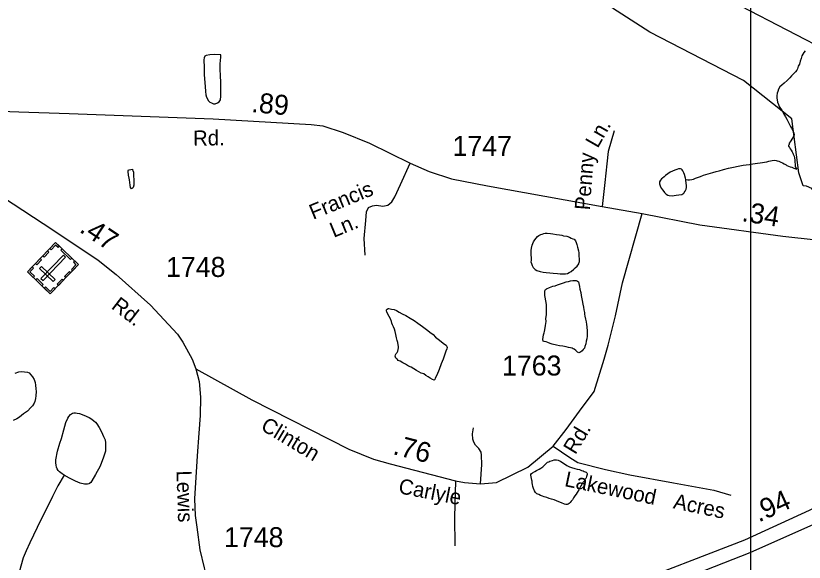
# Model space of a CAD drawing. Extents: x 2126262 to 2293712, y 749403 to 919119.
# Drawn here: x 2220963 to 2225896, y 772432 to 775853 of the extents above; entities that cross this region are included whole.
import ezdxf

# ---------------------------------------------------------------- set-up
doc = ezdxf.new("R2010")
doc.units = 0
for name, color, linetype in [('Exist Cultural Cemetery CELL', 7, 'Continuous'), ('Exist Hydrographic Creek Single Shore', 7, 'Continuous'), ('Exist Hydrographic Misc Water Feature', 7, 'Continuous'), ('Exist Road Non-System Type 51', 7, 'Continuous'), ('Exist Road Non-System Type 51 Label', 7, 'Continuous'), ('Exist Road Primary US Divided Attributed', 7, 'Continuous'), ('Exist Road Primary US Mileage Hundredths English Label', 7, 'Continuous'), ('Exist Road Secondary Mileage Hundredths English Label', 7, 'Continuous'), ('Exist Road Secondary Type 51 Attributed', 7, 'Continuous'), ('Exist Road Secondary Type 51 Label', 7, 'Continuous'), ('Exist Road Secondary Type 51 Number Label', 7, 'Continuous'), ('Map Preparation Inset Cut Line', 7, 'Continuous')]:
    doc.layers.add(name, color=color, linetype=linetype)

msp = doc.modelspace()

# ---------------------------------------------------------------- linework, layer by layer
at = {"layer": 'Exist Cultural Cemetery CELL'}
for points in [[(2221179.4, 774111.4), (2221035.8, 774249.4), (2221212.3, 774433), (2221355.8, 774295)], [(2221236.2, 774410), (2221228.2, 774401.7), (2221212.4, 774417), (2221184.4, 774387.8), (2221176.3, 774395.5), (2221212.3, 774433)], [(2221170.4, 774373), (2221140.4, 774341.8), (2221132.2, 774349.6), (2221162.2, 774380.9)], [(2221306.4, 774326.5), (2221245.3, 774385.3), (2221253.2, 774393.5), (2221314.3, 774334.7)], [(2221124.7, 774325.5), (2221094.7, 774294.2), (2221086.5, 774302.1), (2221116.5, 774333.4)], [(2221121.1, 774208.1), (2221134.5, 774195.2), (2221275.1, 774341.3), (2221261.6, 774354.3)], [(2221065.8, 774280.7), (2221074, 774272.8), (2221051.7, 774249.6), (2221081, 774221.5), (2221073.2, 774213.5), (2221035.8, 774249.5)], [(2221197.1, 774188.8), (2221210, 774202.2), (2221125.2, 774283.8), (2221112.2, 774270.4)], [(2221331.9, 774317.9), (2221324, 774309.6), (2221339.8, 774294.3), (2221311.8, 774265.2), (2221319.9, 774257.5), (2221355.8, 774294.9)], [(2221307.4, 774244.5), (2221277.4, 774213.3), (2221269.2, 774221.2), (2221299.2, 774252.4)], [(2221126, 774162.8), (2221088.6, 774198.7), (2221096.5, 774206.9), (2221133.9, 774171)], [(2221260.8, 774196.1), (2221230.8, 774164.9), (2221222.6, 774172.8), (2221252.6, 774204)], [(2221209.4, 774142.6), (2221201.2, 774150.5), (2221178.9, 774127.3), (2221149.7, 774155.4), (2221141.9, 774147.4), (2221179.4, 774111.4)]]:
    msp.add_lwpolyline(points, close=True, dxfattribs=at)
at = {"layer": 'Exist Hydrographic Creek Single Shore'}
msp.add_lwpolyline([(2225985.9, 774387), (2225979.9, 774406.6), (2225972.7, 774423.7), (2225976.8, 774466.1), (2225985.3, 774509.9), (2225969, 774563.2), (2225976.4, 774612.2), (2225958.7, 774657.9), (2225952.1, 774702.5), (2225968.5, 774735.1), (2225943.4, 774771), (2225910.8, 774785.1), (2225890.1, 774788.4), (2225862, 774869), (2225817.9, 775207.8), (2225515.9, 775446.9), (2224929.8, 775750.9), (2224695.9, 775900.1), (2224661.8, 775972.9), (2224570, 776056.9), (2224418.9, 776122.3)], dxfattribs=at)
at = {"layer": 'Exist Hydrographic Misc Water Feature'}
for points in [[(2222141.4, 775482.2), (2222148, 775410.1), (2222150.5, 775378.6), (2222152.7, 775358.4), (2222156.4, 775342.4), (2222168.9, 775320.6), (2222176.9, 775312.5), (2222188.6, 775306.6), (2222200.9, 775300.7), (2222210.7, 775300.9), (2222224.9, 775306.9), (2222236.8, 775314.8), (2222244.8, 775327), (2222246.2, 775349.1), (2222246.2, 775387.2), (2222245.8, 775431.1), (2222243.5, 775482.9), (2222243.1, 775511), (2222242.9, 775549.2), (2222244.8, 775574.9), (2222246.6, 775590.8), (2222246.6, 775609), (2222206.4, 775610.6), (2222178.5, 775608.4), (2222155, 775604.2), (2222146.6, 775600.2), (2222142.9, 775590.2), (2222140.8, 775576.3), (2222141.4, 775528.4), (2222141.4, 775482.2)], [(2225902.1, 775632.4), (2225894.5, 775622.6), (2225888.1, 775612.6), (2225882.2, 775602.5), (2225876.7, 775584.3), (2225870.5, 775568.2), (2225867.2, 775550), (2225858.8, 775536.3), (2225853.3, 775520.1), (2225849.4, 775512.2), (2225841.4, 775502), (2225831.3, 775490.2), (2225817.4, 775476), (2225805.5, 775463.6), (2225789.7, 775447.7), (2225771.7, 775431.4), (2225755.9, 775417.6), (2225744.4, 775407.1), (2225736.2, 775393.4), (2225730.5, 775379.2), (2225726.2, 775367.3), (2225724.9, 775351.2), (2225724.7, 775337.1), (2225727, 775325.4), (2225729.2, 775311.3), (2225735, 775297.4), (2225739.5, 775285.4), (2225743.2, 775277.5)], [(2225743.2, 775277.5), (2225755.5, 775261.5), (2225767.4, 775241.4), (2225779.9, 775219.7), (2225787.7, 775205.9), (2225795.9, 775188), (2225803.9, 775171.8), (2225810.2, 775159.9), (2225816.4, 775148), (2225822.5, 775136.1), (2225826.2, 775128.2), (2225830.5, 775118.3), (2225832.4, 775108.3), (2225832.8, 775104.1), (2225828.7, 775096.3), (2225822.7, 775086.2), (2225818.6, 775079.9), (2225812.7, 775069.9), (2225809.2, 775063.9), (2225802.8, 775055.9), (2225801, 775047.7), (2225799.1, 775043.9), (2225797.1, 775039.8), (2225798.9, 775035.8), (2225803.3, 775027.9), (2225809.2, 775020.1), (2225815.3, 775011.8), (2225821.5, 775000), (2225825.2, 774992.1), (2225827.2, 774986.1), (2225832, 774978.1), (2225833.8, 774974.2), (2225835.4, 774964.2), (2225837.9, 774948.4), (2225838.1, 774936.2), (2225840, 774924.2), (2225840.4, 774914.4), (2225840.2, 774910.3), (2225842.2, 774904.4), (2225844.5, 774900.3), (2225850.2, 774892.2)], [(2225155.3, 774826.7), (2225167.2, 774824.9), (2225179.1, 774824.7), (2225193, 774827.1), (2225203.3, 774829.2), (2225217, 774835.2), (2225235.1, 774841.4), (2225247.1, 774847.3), (2225266.6, 774855.7), (2225281, 774859.7), (2225294.7, 774863.7), (2225324.7, 774872.1), (2225344.8, 774878), (2225364.6, 774882.3), (2225390.7, 774890.6), (2225422.7, 774898.7), (2225454.3, 774905.3), (2225482.1, 774911.3), (2225514.1, 774917.4), (2225532.4, 774919.9), (2225553.9, 774921.9), (2225574.2, 774926.2), (2225604.1, 774930.1), (2225620.3, 774932.6), (2225635.9, 774934.7), (2225648.2, 774936.5), (2225662.2, 774938.8), (2225673.9, 774942.7), (2225695.8, 774947.1), (2225708.1, 774949.3), (2225720, 774947.1), (2225727.8, 774945.1), (2225737.8, 774941.6), (2225749.9, 774935.3), (2225760, 774931.3), (2225770, 774925.8), (2225782.3, 774919.9), (2225788.3, 774915.7), (2225797.9, 774911.9), (2225808.4, 774907.9), (2225818.2, 774903.9), (2225832.2, 774898.1), (2225850.2, 774892.2)], [(2221668, 774859.1), (2221666.1, 774873.2), (2221665.9, 774883), (2221669.6, 774887.3), (2221673.7, 774889.1), (2221693.8, 774891.4), (2221693.8, 774887.3), (2221695.9, 774883.3), (2221700.2, 774873.3), (2221700.4, 774849.4), (2221702.2, 774827.2), (2221702.4, 774805.2), (2221702.6, 774791.4), (2221698.5, 774777.4), (2221694.4, 774773.2), (2221686.6, 774769.1), (2221680.7, 774777.3), (2221678.2, 774793.1), (2221674.1, 774824.9), (2221670.4, 774845.4), (2221668.4, 774851.4), (2221668, 774859.1)], [(2225155.3, 774826.7), (2225153, 774836.8), (2225146.9, 774858.4), (2225142.6, 774868.4), (2225140.7, 774874.3), (2225136.4, 774882.7), (2225132.7, 774888.5), (2225128.8, 774892.4), (2225122.7, 774894.5), (2225116.7, 774894.2), (2225108.7, 774894.2), (2225098.7, 774890), (2225086.6, 774886.2), (2225072.9, 774880.1), (2225058.5, 774873.8), (2225042.7, 774863.6), (2225028.8, 774853.5), (2225019.1, 774843.6), (2225009.3, 774835.4), (2225003.1, 774831.4), (2224997, 774823.4), (2224991, 774813.4), (2224991.7, 774801.1), (2224995.3, 774787.2), (2225001.9, 774773.2), (2225011.7, 774761.6), (2225021.8, 774745.5), (2225031.8, 774735.8), (2225041.9, 774729.8), (2225052.1, 774727.9), (2225070, 774726), (2225095.8, 774730.2), (2225111.8, 774732.2), (2225129.7, 774734.4), (2225142.2, 774742.7), (2225145.6, 774746.6), (2225151.8, 774754.6), (2225157.5, 774766.7), (2225159.2, 774776.6), (2225159.4, 774790.8), (2225157.1, 774804.5), (2225155.1, 774822.7), (2225155.3, 774826.7)], [(2224187.6, 774307.9), (2224189.7, 774323.8), (2224189.7, 774336), (2224187.4, 774357.9), (2224187.2, 774382.2), (2224189.1, 774398.6), (2224195, 774416.7), (2224202.6, 774437.1), (2224210.4, 774450.9), (2224218.6, 774461.1), (2224228.2, 774471.4), (2224236.7, 774477.4), (2224248.1, 774483.4), (2224256.1, 774485.4), (2224266.2, 774489.6), (2224276.4, 774491.7), (2224288.1, 774491.5), (2224308.2, 774489.7), (2224324.2, 774488.1), (2224345.9, 774484), (2224364.2, 774480.4), (2224380.4, 774478.4), (2224390.4, 774474.5), (2224410.5, 774472.6), (2224428.2, 774466.7), (2224438.2, 774460.8), (2224448.7, 774456.8), (2224456.5, 774453.1), (2224464.7, 774443), (2224468.4, 774433.1), (2224472.9, 774421), (2224477, 774405), (2224483.1, 774380.6), (2224485.4, 774368.4), (2224485.4, 774348.2), (2224487.4, 774330), (2224487.4, 774310.1)], [(2224187.6, 774307.9), (2224194, 774289.9), (2224200.2, 774276), (2224212, 774264.1), (2224224.3, 774258.2), (2224244.2, 774252.3), (2224263.9, 774246.5), (2224282.4, 774244.5), (2224304.1, 774242.8), (2224326.5, 774240.7), (2224352.1, 774239.3), (2224368.3, 774237.2), (2224388.4, 774237.5), (2224402.3, 774237.4), (2224414.2, 774239.7), (2224426.3, 774245.9), (2224438.2, 774251.8), (2224453.8, 774266.1), (2224463.6, 774274), (2224475.7, 774285.9), (2224485.4, 774300.3), (2224487.4, 774310.1)], [(2224507.1, 774070.6), (2224511.6, 774046.4), (2224515.9, 774028.8), (2224517.8, 774012.6), (2224522.1, 773994.6), (2224522.1, 773984.8), (2224524.3, 773972.7), (2224528.2, 773952.6), (2224532.7, 773936.5), (2224534.4, 773920.9), (2224536.8, 773904.7), (2224538.9, 773878.8), (2224538.9, 773861), (2224537.5, 773846.6), (2224535.2, 773830.7), (2224531.5, 773816.6), (2224529.9, 773798.6), (2224523.9, 773783), (2224521.7, 773772.7), (2224513.7, 773762.6), (2224506.1, 773754.8), (2224496, 773746.6), (2224490.3, 773744.6), (2224486, 773742.4), (2224478.2, 773746.4), (2224466.3, 773756.3), (2224456.1, 773766), (2224449.9, 773768.1), (2224443.8, 773771.9), (2224433.9, 773773.8), (2224422, 773776), (2224406, 773779.6), (2224385.9, 773783.5), (2224365.6, 773787.4), (2224345.9, 773791.2), (2224320.1, 773797), (2224307.6, 773801), (2224291.6, 773806.6), (2224281.6, 773810.6), (2224269.7, 773812.8), (2224263.9, 773816.5), (2224261.7, 773826.6), (2224263.1, 773840.5), (2224265.6, 773854.8), (2224269.3, 773866.8), (2224271.3, 773876.7), (2224275, 773898.8), (2224276.8, 773912.7), (2224278.7, 773926.6), (2224280.7, 773938.5), (2224280.3, 773956.8), (2224282.4, 773968.7), (2224284.2, 773982.6), (2224284.2, 773994.8), (2224284.2, 774012.6), (2224283.8, 774026.5), (2224283.6, 774042.7), (2224281.8, 774056.8), (2224279.9, 774068.4), (2224275.4, 774090.6), (2224273.4, 774100.7), (2224273.4, 774108.4), (2224272.9, 774116.5), (2224273.2, 774122.6), (2224273.2, 774130.7), (2224275.2, 774134.5), (2224277, 774138.6), (2224282.8, 774142.6), (2224302.9, 774151), (2224323, 774158.9), (2224339, 774163), (2224352.7, 774169), (2224372.4, 774175.4), (2224390.4, 774181.6), (2224406.8, 774187.6), (2224420.8, 774189.6), (2224434.5, 774194), (2224448.5, 774195.9), (2224460.4, 774196.1), (2224468.6, 774196.1), (2224478.4, 774192.2), (2224484.8, 774186.4), (2224486.4, 774176.4), (2224490.7, 774158.3), (2224492.8, 774140.2), (2224499.3, 774120.5), (2224501.4, 774102.3), (2224507.1, 774070.6)], [(2223507.1, 773906.4), (2223541.3, 773882.6), (2223553.4, 773872.7), (2223573.7, 773857), (2223589.7, 773841.2), (2223606.1, 773827.4), (2223623.8, 773813.4), (2223637.9, 773803.5), (2223646.3, 773797.8), (2223655.9, 773789.8), (2223660.3, 773781.9), (2223662.1, 773775.9), (2223660.5, 773767.7), (2223654.1, 773753.6), (2223646.7, 773733.6), (2223636.9, 773703.4), (2223625.2, 773673.6), (2223611.4, 773637.5), (2223597.7, 773603.1), (2223588.1, 773583.1), (2223584.2, 773575.1), (2223580.1, 773571.3), (2223569.6, 773574.9), (2223556.1, 773585), (2223543.8, 773593), (2223529.8, 773600.8), (2223515.7, 773610.6), (2223499.7, 773616.3), (2223485.8, 773624.4), (2223471.2, 773632.3), (2223453.4, 773641.9), (2223437.6, 773652), (2223421, 773659.8), (2223400.9, 773671.8), (2223385.1, 773679.4), (2223369.1, 773689.6), (2223356.8, 773695.4), (2223351, 773701.2), (2223346.9, 773705), (2223340.8, 773709.2), (2223338.9, 773715.2), (2223336.9, 773721.2), (2223338.5, 773729), (2223342.6, 773737.4), (2223348.6, 773745.4), (2223352.9, 773753.2), (2223356.2, 773763.3), (2223358.2, 773773.1), (2223358.4, 773781.2), (2223356.2, 773793.3), (2223354.1, 773807), (2223349.8, 773819), (2223345.9, 773837), (2223343.9, 773847.1), (2223341.6, 773857.2), (2223337.7, 773876.8), (2223333.2, 773890.9), (2223327.5, 773905.1), (2223321.1, 773917.1), (2223317, 773929), (2223313.3, 773938.9), (2223306.9, 773954.9), (2223298.9, 773970.7), (2223290.5, 773984.5), (2223284.4, 773998.5), (2223283, 774004.4), (2223282.5, 774012.5), (2223286.6, 774016.8), (2223292.4, 774020.8), (2223298.3, 774020.7), (2223314.3, 774016.7), (2223330.1, 774013), (2223344.5, 774006.8), (2223362.9, 773997.2), (2223380.8, 773987.2), (2223402.7, 773975.8), (2223431, 773959.7), (2223456.8, 773944), (2223479.2, 773928.1), (2223507.1, 773906.4)], [(2220958.7, 773615.7), (2220982.7, 773623.9), (2221000.7, 773626), (2221018.4, 773624.2), (2221036.4, 773620.7), (2221046.9, 773616.7), (2221058.5, 773604.8), (2221068.8, 773592.7), (2221079.1, 773574.9), (2221085.4, 773556.9), (2221086.8, 773540.8), (2221089.3, 773516.9), (2221091.4, 773500.8), (2221089.7, 773473.1), (2221085.8, 773457), (2221081.9, 773436.9), (2221077.8, 773427), (2221068.2, 773410.6), (2221058.1, 773400.7), (2221036.6, 773378.4), (2221012.2, 773360.6), (2220986.4, 773340.2), (2220970.6, 773330), (2220946.4, 773319.8)], [(2221267.1, 772976.1), (2221253.1, 772984.3), (2221237.2, 772998.1), (2221229.2, 773006.2), (2221222.6, 773016.1), (2221218.9, 773026), (2221216.4, 773040.2), (2221214.6, 773053.8), (2221214.6, 773071.7), (2221223.8, 773127.9), (2221239.6, 773176.2), (2221249.7, 773205.9), (2221263.4, 773260.2), (2221276.9, 773306.1), (2221288.4, 773334.3), (2221294.4, 773344.4), (2221306.5, 773356.3), (2221312.2, 773360.3), (2221318.6, 773364.3), (2221326.6, 773366.7), (2221336.2, 773366.4), (2221348.3, 773364.6), (2221362.4, 773362.9), (2221388.5, 773352.9), (2221422.3, 773337.2), (2221438.5, 773327.5), (2221452.7, 773317.3), (2221462.9, 773307.6), (2221470.5, 773297.5), (2221484.9, 773275.9), (2221498.8, 773247.8), (2221512.9, 773218.1), (2221521.6, 773197.7), (2221525.2, 773180.1), (2221525.7, 773154.1), (2221523.8, 773128), (2221512.1, 773090), (2221490.4, 773033.7), (2221462.9, 772981.4), (2221439.3, 772941.6), (2221433.4, 772931.5), (2221425.2, 772925.5), (2221419.4, 772921.5), (2221411.4, 772919.4), (2221403.4, 772919.4), (2221393.4, 772921.3), (2221367.2, 772926.9), (2221337.2, 772938.8), (2221298.9, 772958.3), (2221267.1, 772976.1)], [(2224428, 773028.3), (2224439.7, 773024.5), (2224460.4, 773018.5), (2224476.4, 773014.5), (2224490.1, 773012.8), (2224502.2, 773006.9), (2224512.2, 773003), (2224520.4, 772998.9), (2224526.2, 772997.2), (2224532.1, 772995.1), (2224536.2, 772991.2), (2224538.5, 772987.2), (2224538.3, 772981.2), (2224536.4, 772975), (2224534.6, 772969.2), (2224532.3, 772961), (2224530.5, 772955.2), (2224526.4, 772950.9), (2224518.6, 772939.2), (2224510.8, 772931), (2224505.1, 772918.9), (2224498.9, 772910.9), (2224494.8, 772901), (2224485.2, 772884.5), (2224474.9, 772868.6), (2224469.4, 772858.5), (2224461.6, 772846.7), (2224453.6, 772834.5), (2224445.6, 772822.4), (2224437.4, 772814.3), (2224431.9, 772806.2), (2224425.7, 772800.2), (2224420, 772794.2), (2224413.8, 772792.3), (2224404, 772792.1), (2224395.8, 772794.2), (2224377.9, 772803.8), (2224361.9, 772809.9), (2224345.7, 772815.5), (2224331.6, 772821.4), (2224315.6, 772827.4), (2224299.6, 772831.4), (2224285.7, 772837.2), (2224269.9, 772841.2), (2224259.8, 772844.7), (2224247.3, 772848.7), (2224235.6, 772854.9), (2224229.3, 772858.7), (2224223.3, 772860.8), (2224219.2, 772864.6), (2224215.3, 772868.5), (2224209.4, 772878.7), (2224203.2, 772892.7), (2224199.1, 772906.3), (2224196.9, 772918.4), (2224194.6, 772928.4), (2224195, 772938.5), (2224192.6, 772946.2), (2224190.7, 772956.2), (2224188.7, 772966.2), (2224186.4, 772976.3), (2224186.2, 772980.4), (2224190.3, 772986.3), (2224196.3, 772992.2), (2224210.4, 773000.7), (2224220.5, 773006.5), (2224230.1, 773010.7), (2224237.9, 773014.8), (2224248.3, 773020.9), (2224261.9, 773029), (2224274.2, 773040.9), (2224282, 773049.1), (2224290, 773057.2), (2224298, 773059.3), (2224305.5, 773063.4), (2224313.8, 773067.4), (2224321.7, 773069.4), (2224331.4, 773073.3), (2224339.6, 773073.7), (2224345.9, 773073.5), (2224355.8, 773071.6), (2224361.9, 773067.8), (2224367.5, 773065.8), (2224373.6, 773061.6), (2224383.7, 773056), (2224392.1, 773049.9), (2224401.7, 773044), (2224411.8, 773038), (2224420.2, 773032.3), (2224428, 773028.3)], [(2221267.1, 772976.1), (2221225.5, 772910.2), (2221194.1, 772843.9), (2221158.4, 772769.8), (2221120.9, 772697.6), (2221051.8, 772553.1), (2221028.4, 772503), (2221010.6, 772458.7), (2220985.1, 772370.4), (2220969.4, 772298.6), (2220964.4, 772250.6), (2220966.5, 772216.7), (2220972.4, 772184.5), (2220982.9, 772154.5), (2220992.7, 772132.7)]]:
    msp.add_lwpolyline(points, dxfattribs=at)
at = {"layer": 'Exist Road Non-System Type 51'}
for points in [[(2224707.6, 775133.1), (2224669.5, 775002.9), (2224661.5, 774925.1), (2224648.8, 774809.1), (2224632.9, 774658.3)], [(2223148.6, 774353.9), (2223142.4, 774458.2), (2223154.3, 774570), (2223156.8, 774625.2), (2223170.6, 774651.6), (2223194.5, 774662.9), (2223219.6, 774666.7), (2223259.8, 774661.7), (2223291.2, 774666.7), (2223316.3, 774686.8), (2223335.1, 774718.2), (2223369.7, 774797.3), (2223430, 774930.4)], [(2223871.5, 772922.5), (2223879.4, 773043.2), (2223877.8, 773102), (2223874.6, 773121), (2223860.3, 773143.3), (2223839.7, 773165.5), (2223830.2, 773183), (2223822.2, 773202), (2223820.6, 773235.4), (2223827, 773273.5)], [(2224325.6, 773159.1), (2224429.9, 773087.4), (2224480.1, 773056.7), (2224652, 773011.5), (2224804.4, 772979.7), (2225079.2, 772928.9), (2225331.7, 772882.8), (2225436.5, 772851.1)], [(2223715, 772941.6), (2223708.7, 772712.9), (2223711.1, 772533.4)]]:
    msp.add_lwpolyline(points, dxfattribs=at)
at = {"layer": 'Exist Road Primary US Divided Attributed'}
for points in [[(2227424.2, 773604.6), (2227337.8, 773546.9), (2227102.3, 773394.4), (2226776.6, 773202.6), (2226529.8, 773059.3), (2226190.4, 772881.6), (2225926.7, 772754.9), (2225523.3, 772570.7), (2224745.1, 772268.9), (2224138, 772041.6), (2223699.4, 771866.5), (2223208.5, 771674.5), (2222923.7, 771565.3)], [(2223003.1, 771498.9), (2223245, 771594.8), (2223746.4, 771786.8), (2224170.7, 771956.7), (2224781.7, 772187.9), (2225557.2, 772492.3), (2225956.7, 772670), (2226232.2, 772801.9), (2226571.6, 772987.4), (2226813.6, 773121.7), (2227141.5, 773315.8), (2227386.3, 773470.7), (2227506.4, 773557)]]:
    msp.add_lwpolyline(points, dxfattribs=at)
at = {"layer": 'Exist Road Secondary Type 51 Attributed'}
for points in [[(2224102.9, 777886.3), (2224146.3, 777767.6), (2224191.5, 777628.7), (2224332.9, 777174.2), (2224502.5, 776659.4), (2224552.7, 776565.8), (2224615.5, 776475), (2224743.2, 776341.6), (2224919.1, 776215.9), (2225208, 776066.5), (2226078.2, 775614.6), (2226420.9, 775435.1), (2226518.6, 775352.6), (2226621.9, 775240.9), (2226672.1, 775134.7), (2226739.8, 774970.6), (2226756.5, 774857.4), (2226756.5, 774728.9), (2226753, 774534.4), (2226714.9, 774408.9), (2226672, 774316.8), (2226543.4, 774130.3)], [(2220269, 775279), (2220643.7, 775262.7), (2220982.7, 775252), (2221296.7, 775240.6), (2222197.9, 775208), (2222812, 775172.8), (2222884.9, 775162.8), (2223011.7, 775122.6), (2223176.9, 775054.8), (2223430, 774930.4), (2223549.9, 774877.7), (2223689.3, 774832.5), (2223914.8, 774787.2), (2224632.9, 774658.3), (2224882.3, 774615.4)], [(2220269, 775279), (2220289.7, 775178.9), (2220315.8, 775130), (2220348.4, 775085.4), (2220385.9, 775054.9), (2220886.9, 774714.4), (2221194.7, 774513.2), (2221479.7, 774321.7), (2221590.7, 774233.6), (2221806.6, 774040), (2221975.7, 773859.4), (2222009.5, 773808.3), (2222066, 773703.9), (2222090.5, 773643)], [(2222090.5, 773643), (2222439.7, 773449.3), (2223047.3, 773138.5), (2223201.3, 773076.6), (2223306.1, 773048), (2223715, 772941.6), (2223770.6, 772930.5), (2223871.5, 772922.5), (2223970.4, 772930.5), (2224166.5, 773026.2), (2224325.6, 773159.1), (2224406.6, 773262.4), (2224490.8, 773376.7), (2224582.7, 773501.3), (2224644.6, 773702.7), (2224668.7, 773789.6), (2224715.5, 773973.8), (2224760, 774180.3), (2224882.3, 774615.4)], [(2224882.3, 774615.4), (2225242.6, 774542.8), (2225762.5, 774472.3), (2225971.7, 774449), (2226094.6, 774421.8), (2226193.6, 774389.2), (2226289.4, 774338.1), (2226394.9, 774257.6), (2226475.4, 774189), (2226543.4, 774130.3)], [(2222090.5, 773643), (2222110.1, 773562.5), (2222119.9, 773464.6), (2222116.1, 773350.3), (2222109.5, 773239.4), (2222098.1, 773098), (2222082.3, 772828.2), (2222086.7, 772723.8), (2222095.9, 772652), (2222114.4, 772508.4), (2222141.1, 772397.4), (2222169.4, 772287.6), (2222198.7, 772211.4), (2222247.1, 772124.4), (2222286.3, 772071.1), (2222328.7, 772021.1), (2222382, 771968.9), (2222429.9, 771929.7), (2222641.5, 771768.7), (2222923.7, 771565.3)]]:
    msp.add_lwpolyline(points, dxfattribs=at)
at = {"layer": 'Map Preparation Inset Cut Line'}
msp.add_lwpolyline([(2225559.9, 781102.8), (2225559.9, 762528.3), (2216266.9, 762528.3), (2206391.5, 779996.5), (2206391.5, 781102.8)], close=True, dxfattribs=at)

# ---------------------------------------------------------------- texts
at = {"layer": 'Exist Road Non-System Type 51 Label'}
for s, rotation, p in [('Ln.', 60.2796, (2224603.9, 775019)), ('Penny', 85.4796, (2224554.3, 774633.2)), ('Francis', 22.3541, (2222823.6, 774575.1)), ('Ln.', 22.3541, (2222952.3, 774461.9)), ('Lakewood', 348.1862, (2224392.1, 772908.9)), ('Acres', 348.1862, (2225072, 772769.9))]:
    msp.add_text(s, height=95, rotation=rotation, dxfattribs=at).set_placement(p)
at = {"layer": 'Exist Road Primary US Mileage Hundredths English Label'}
msp.add_text('.94', height=125, rotation=24.5417, dxfattribs=at).set_placement((2225611.7, 772679.8))
at = {"layer": 'Exist Road Secondary Mileage Hundredths English Label'}
for s, rotation, p in [('.89', 354.8475, (2222434.6, 775250)), ('.34', 350.9047, (2225501.4, 774567.7)), ('.47', 326.4279, (2221355.6, 774503.3)), ('.76', 345.4154, (2223317.2, 773109.7))]:
    msp.add_text(s, height=125, rotation=rotation, dxfattribs=at).set_placement(p)
at = {"layer": 'Exist Road Secondary Type 51 Label'}
for s, rotation, p in [('Rd.', 0.8897, (2222073.3, 775038.9)), ('Rd.', 322.5366, (2221555.4, 774024.1)), ('Clinton', 328.9162, (2222489.5, 773264.8)), ('Rd.', 58.9616, (2224464.2, 773101.2)), ('Lewis', 271.9145, (2221968.5, 773004.6)), ('Carlyle', 348.9689, (2223352.8, 772864.6))]:
    msp.add_text(s, height=95, rotation=rotation, dxfattribs=at).set_placement(p)
at = {"layer": 'Exist Road Secondary Type 51 Number Label'}
for s, p in [('1747', (2223695.7, 774975.3)), ('1748', (2221903.4, 774217.6)), ('1763', (2224005.4, 773600.6)), ('1748', (2222266.4, 772526.2))]:
    msp.add_text(s, height=125, dxfattribs=at).set_placement(p)

doc.saveas('drawing.dxf')
